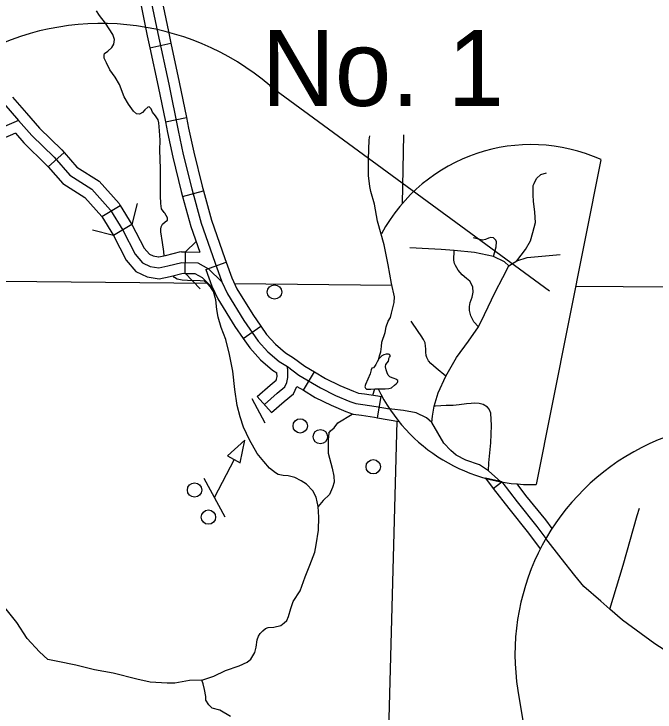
# Model space of a CAD drawing. Extents: x 22866 to 28196, y 1324810 to 1328105.
# Drawn here: x 25027.1 to 25134.1, y 1326082.2 to 1326198.9 of the extents above; entities that cross this region are included whole.
import ezdxf

# ---------------------------------------------------------------- set-up
doc = ezdxf.new("R2010")
doc.units = 0
for name, color, linetype in [('Level 31', 7, 'Continuous'), ('Level 32', 7, 'Continuous'), ('Level 35', 7, 'Continuous'), ('Level 38', 7, 'Continuous'), ('Level 45', 7, 'Continuous'), ('Level 5', 7, 'Continuous'), ('Level 56', 7, 'Continuous'), ('Level 63', 7, 'Continuous')]:
    doc.layers.add(name, color=color, linetype=linetype)

msp = doc.modelspace()

# ---------------------------------------------------------------- linework, layer by layer
at = {"layer": 'Level 31'}
for p, q in [((25108.51, 1326120.69), (25105.77, 1326121.31)), ((25107.09, 1326119.59), (25108.51, 1326120.69))]:
    msp.add_line(p, q, dxfattribs=at)
for points in [[(25102.49, 1326124.35), (25100.89, 1326125.16), (25100.02, 1326125.95), (25098.85, 1326127.19), (25096.85, 1326130.61)], [(25108.35, 1326120.72), (25106.32, 1326122.55), (25104.77, 1326123.55), (25102.49, 1326124.35)], [(25105.77, 1326121.31), (25107.09, 1326119.59)], [(25108.51, 1326120.69), (25111.08, 1326117.34), (25114.39, 1326113.23), (25115.89, 1326111.25)], [(25111.03, 1326120.36), (25112.5, 1326118.45), (25115.81, 1326114.34), (25116.9, 1326112.9)], [(25107.09, 1326119.59), (25109.67, 1326116.23), (25112.97, 1326112.12), (25114.95, 1326109.52)], [(25140.41, 1326089.55), (25137.17, 1326091.66), (25134.1, 1326093.62), (25128.65, 1326097.59), (25126.55, 1326099.42), (25125.04, 1326100.75), (25122.21, 1326103.2), (25120.69, 1326105.03), (25118.45, 1326107.93), (25115.89, 1326111.25)]]:
    msp.add_lwpolyline(points, dxfattribs=at)
at = {"layer": 'Level 32'}
for p, q in [((25049.75, 1326193.26), (25053.27, 1326194.01)), ((25052.33, 1326180.87), (25055.86, 1326181.59)), ((25032.74, 1326173.36), (25035.45, 1326175.73)), ((25055.21, 1326168.4), (25058.68, 1326169.35)), ((25041.73, 1326165.04), (25044.81, 1326166.91)), ((25059.1, 1326156.21), (25062.49, 1326157.42)), ((25065.31, 1326144.68), (25068.26, 1326146.74)), ((25075.39, 1326136.01), (25077.24, 1326139.1)), ((25070.08, 1326132.28), (25067.69, 1326134.98)), ((25087.76, 1326131.43), (25088.37, 1326134.98))]:
    msp.add_line(p, q, dxfattribs=at)
for points in [[(24974.12, 1326207.32), (24980.82, 1326207.4), (24985.53, 1326207.25), (24992.15, 1326206.59), (24999.21, 1326204.89), (25006.05, 1326202.68), (25009.21, 1326201.14), (25011.5, 1326199.59), (25013.26, 1326197.38), (25015.61, 1326193.85), (25019.15, 1326190.39), (25024.22, 1326185.16), (25027.79, 1326181.11)], [(25050.45, 1326206.43), (25051.74, 1326201.32), (25052.85, 1326195.99), (25053.27, 1326194.01)], [(25046.96, 1326205.55), (25048.23, 1326200.52), (25049.32, 1326195.25), (25049.75, 1326193.26)], [(25053.27, 1326194.01), (25054.65, 1326187.51), (25055.86, 1326181.59)], [(25049.75, 1326193.26), (25051.13, 1326186.77), (25052.33, 1326180.87)], [(25026.79, 1326184.97), (25029.15, 1326182.3), (25031.31, 1326179.82), (25035.05, 1326176.19), (25035.45, 1326175.73)], [(25027.79, 1326181.11), (25023.17, 1326179.17), (25016.86, 1326177), (25012.59, 1326175.79), (25009.07, 1326174.34), (25005.41, 1326172.55), (25002.24, 1326171.2), (24998.62, 1326169.51), (24996.24, 1326168.16), (24993.66, 1326166.82), (24991.7, 1326165.56), (24989.21, 1326163.53), (24986.97, 1326161.49), (24982.21, 1326157.07), (24980.6, 1326155.52), (24977.36, 1326152.17), (24975.08, 1326150.33), (24971.91, 1326147.77), (24969.32, 1326145.43), (24968.29, 1326144.08), (24967.32, 1326142.73)], [(25027.79, 1326181.11), (25030.01, 1326178.58), (25033.74, 1326174.95), (25036.39, 1326171.93), (25040.08, 1326169.59), (25043.17, 1326166.13), (25045.23, 1326162.75), (25047.29, 1326158.77), (25048.54, 1326157.3), (25049.8, 1326156.71), (25051.27, 1326156.49), (25052.74, 1326156.78), (25055.09, 1326157.37), (25057.74, 1326157.3), (25059.56, 1326156.31), (25061.75, 1326154.11)], [(25052.33, 1326180.87), (25052.7, 1326179.08), (25053.57, 1326174.99), (25054.99, 1326169.21), (25055.21, 1326168.4)], [(25055.86, 1326181.59), (25056.22, 1326179.81), (25057.08, 1326175.79), (25058.48, 1326170.11), (25058.68, 1326169.35)], [(25027.29, 1326178.95), (25023.81, 1326177.49), (25017.4, 1326175.28), (25016.4, 1326175)], [(25027.29, 1326178.95), (25028.7, 1326177.34), (25032.44, 1326173.71), (25032.74, 1326173.36)], [(25035.45, 1326175.73), (25037.57, 1326173.31), (25041.26, 1326170.98), (25044.63, 1326167.21), (25044.81, 1326166.91)], [(25032.74, 1326173.36), (25035.21, 1326170.55), (25038.91, 1326168.21), (25041.72, 1326165.06), (25041.73, 1326165.04)], [(25113.74, 1326168.63), (25113.77, 1326170.24), (25113.94, 1326170.59), (25114.32, 1326171.38), (25115.05, 1326172.07), (25115.98, 1326172.35)], [(25058.68, 1326169.35), (25060.02, 1326164.46), (25062.28, 1326158.01), (25062.49, 1326157.42)], [(25055.21, 1326168.4), (25056.58, 1326163.39), (25058.08, 1326159.09)], [(25111.01, 1326157.65), (25112.46, 1326159.55), (25113.29, 1326160.97), (25113.7, 1326162.38), (25114.15, 1326164.07), (25114.01, 1326165.8), (25113.84, 1326167.59), (25113.74, 1326168.63)], [(25044.81, 1326166.91), (25046.75, 1326163.72), (25043.66, 1326161.87)], [(25041.73, 1326165.04), (25043.66, 1326161.87)], [(25046.75, 1326163.72), (25048.8, 1326159.78), (25049.66, 1326158.76), (25050.32, 1326158.45), (25051.16, 1326158.32)], [(25043.66, 1326161.87), (25045.79, 1326157.76), (25047.42, 1326155.84), (25049.27, 1326154.97), (25050.62, 1326154.76)], [(25109.7, 1326156.8), (25108.98, 1326157.49), (25107.15, 1326158.35), (25103.95, 1326159.01), (25100.57, 1326159.36), (25098.39, 1326159.52), (25096.29, 1326159.63), (25093.15, 1326159.83)], [(25051.16, 1326158.32), (25051.22, 1326158.32), (25052.34, 1326158.54), (25054.89, 1326159.18), (25055.03, 1326159.17), (25055.71, 1326159.16)], [(25055.66, 1326155.55), (25055.71, 1326159.16), (25058.08, 1326159.09)], [(25109.7, 1326156.8), (25111.01, 1326157.65), (25112.74, 1326158.21), (25118.29, 1326158.72)], [(25062.49, 1326157.42), (25063.42, 1326154.8), (25064.28, 1326152.99), (25066.93, 1326148.65), (25068.26, 1326146.74)], [(25059.1, 1326156.21), (25060.09, 1326153.42), (25061.11, 1326151.28), (25063.91, 1326146.68), (25065.31, 1326144.68)], [(25096.85, 1326130.61), (25096.92, 1326131.67), (25097.2, 1326133.34), (25097.89, 1326135.57), (25099.15, 1326138.39), (25100.96, 1326141.48), (25102.96, 1326144.24), (25104.61, 1326146.6), (25105.65, 1326148.67), (25107.4, 1326152.43), (25108.7, 1326154.87), (25109.7, 1326156.8)], [(25050.62, 1326154.76), (25051.31, 1326154.66), (25053.13, 1326155.03), (25055.29, 1326155.56), (25055.29, 1326155.56), (25055.66, 1326155.55)], [(25055.66, 1326155.55), (25057.26, 1326155.51), (25058.47, 1326154.86), (25060.26, 1326153.06)], [(25068.26, 1326146.74), (25069.24, 1326145.33), (25070.71, 1326143.71), (25072.38, 1326142.28), (25073.72, 1326141.45), (25075.62, 1326140.06), (25077.24, 1326139.1)], [(25065.31, 1326144.68), (25066.42, 1326143.09), (25068.2, 1326141.12), (25070.25, 1326139.37), (25070.96, 1326138.93)], [(25068.89, 1326133.63), (25071.01, 1326135.52), (25072.27, 1326136.56), (25072.62, 1326137.3), (25072.79, 1326138.17), (25072.76, 1326139.18), (25072.71, 1326139.96)], [(25067.69, 1326134.98), (25069.84, 1326136.88), (25070.81, 1326137.69), (25070.89, 1326137.87), (25070.98, 1326138.31), (25070.96, 1326138.93)], [(25077.24, 1326139.1), (25079.09, 1326137.98), (25081.49, 1326136.8), (25083.78, 1326135.84), (25084.61, 1326135.53), (25085.59, 1326135.39), (25087.82, 1326135.08), (25088.37, 1326134.98)], [(25070.08, 1326132.28), (25072.19, 1326134.15), (25073.72, 1326135.43), (25074.31, 1326136.65)], [(25074.31, 1326136.65), (25075.39, 1326136.01)], [(25075.39, 1326136.01), (25077.36, 1326134.82), (25080, 1326133.52), (25082.47, 1326132.48), (25083.71, 1326132.03), (25085.08, 1326131.83), (25087.26, 1326131.52), (25087.76, 1326131.43)], [(25088.37, 1326134.98), (25088.54, 1326134.95)], [(25096.85, 1326130.61), (25095.95, 1326131.43), (25094.2, 1326132.23), (25092.09, 1326132.61), (25090.13, 1326132.85), (25089.78, 1326132.91)], [(25101.4, 1326133.58), (25100.37, 1326133.44), (25099.2, 1326133.48), (25097.47, 1326133.37), (25097.2, 1326133.34)], [(25106.32, 1326122.55), (25106.33, 1326123.88), (25106.67, 1326127.23), (25106.78, 1326130.13), (25106.71, 1326132.17), (25106.43, 1326132.86), (25106.12, 1326133.2), (25105.4, 1326133.62), (25104.74, 1326133.79), (25104.02, 1326133.86), (25103.43, 1326133.82), (25102.6, 1326133.76), (25101.4, 1326133.58)], [(25087.76, 1326131.43), (25091.32, 1326130.81)], [(25126.55, 1326099.42), (25128.78, 1326106.81), (25131.13, 1326115.1), (25131.51, 1326116.3)]]:
    msp.add_lwpolyline(points, dxfattribs=at)
at = {"layer": 'Level 35'}
for points in [[(25044.67, 1326187.13), (25043.94, 1326188.35), (25043.05, 1326189.55), (25042.51, 1326190.73), (25042.14, 1326191.51), (25042.14, 1326191.77), (25042.11, 1326192.04), (25042.19, 1326192.3), (25042.74, 1326192.66), (25043.42, 1326193.27), (25043.73, 1326193.87), (25043.84, 1326194.65), (25043.58, 1326195.44), (25042.35, 1326197.37), (25041.36, 1326198.63), (25040.86, 1326199.41)], [(25052.12, 1326165.73), (25051.7, 1326166.34), (25051.6, 1326167.21), (25051.54, 1326168.51), (25051.54, 1326170.95), (25051.54, 1326173.07), (25051.39, 1326176.13), (25051.44, 1326177.78), (25051.36, 1326179.37), (25051.26, 1326180.68), (25051.13, 1326181.22), (25050.66, 1326181.87), (25050.16, 1326182.5), (25049.95, 1326183.07), (25049.61, 1326183.36), (25049.4, 1326183.31), (25048.88, 1326182.87), (25048.49, 1326182.45), (25048.04, 1326182.16), (25047.52, 1326182.19), (25047, 1326182.63), (25046.16, 1326183.81), (25045.48, 1326185.04), (25044.67, 1326187.13)], [(25090.59, 1326151.65), (25090.12, 1326153.86), (25089.55, 1326156.95), (25088.85, 1326160.33), (25087.78, 1326164.26), (25087.28, 1326167.11), (25086.64, 1326169.22), (25086.47, 1326170.04), (25086.27, 1326171.89), (25086.24, 1326174.64), (25086.37, 1326177.85), (25086.47, 1326178.54)], [(25052.15, 1326158.5), (25052.07, 1326159.19), (25051.86, 1326160.71), (25051.57, 1326162.46), (25051.57, 1326162.91), (25051.65, 1326163.35), (25051.88, 1326163.77), (25052.28, 1326164.14), (25052.67, 1326164.45), (25052.69, 1326164.82), (25052.49, 1326165.21), (25052.22, 1326165.6), (25052.12, 1326165.73)], [(25059.23, 1326153.96), (25058.86, 1326154.25), (25058.13, 1326154.3), (25056.04, 1326154.35), (25055.13, 1326154.41), (25054.31, 1326154.59), (25053.87, 1326154.85), (25053.65, 1326155.15)], [(25063.93, 1326136.13), (25063.59, 1326139.2), (25063.07, 1326141.97), (25062.42, 1326144.48), (25061.63, 1326146.5), (25061.14, 1326148.22), (25060.95, 1326149.5), (25060.74, 1326151.13), (25060.37, 1326152.5), (25059.95, 1326153.19), (25059.23, 1326153.96)], [(25087.99, 1326141.26), (25088.11, 1326141.76), (25088.31, 1326142.43), (25088.41, 1326143.3), (25088.48, 1326144.07), (25089.02, 1326145.68), (25089.18, 1326146.62), (25089.52, 1326147.56), (25089.92, 1326148.16), (25090.12, 1326148.9), (25090.26, 1326149.57), (25090.56, 1326150.68), (25090.59, 1326151.65)], [(25087.66, 1326136.25), (25089.06, 1326136.23), (25089.67, 1326136.28), (25090.12, 1326136.42), (25090.61, 1326136.88), (25090.87, 1326137.1), (25091.1, 1326137.3), (25091.15, 1326137.5), (25091.13, 1326137.66), (25090.8, 1326137.89), (25090.52, 1326137.99), (25090.19, 1326138.08), (25089.81, 1326138.24), (25089.55, 1326138.55), (25089.39, 1326138.94), (25089.2, 1326139.41), (25089.09, 1326139.93), (25089.09, 1326140), (25089.16, 1326140.33), (25089.37, 1326140.58), (25089.62, 1326140.89), (25089.63, 1326141.17), (25089.63, 1326141.31), (25089.74, 1326141.52), (25089.93, 1326141.78), (25089.77, 1326141.97), (25089.58, 1326142.02), (25089.18, 1326142.02), (25088.83, 1326141.94), (25088.48, 1326141.74), (25087.99, 1326141.26), (25087.72, 1326140.75), (25087.49, 1326140.3), (25087.28, 1326139.96), (25087.09, 1326139.76), (25086.84, 1326139.7), (25086.72, 1326139.41), (25086.53, 1326138.78), (25086.15, 1326137.84), (25085.73, 1326136.98), (25085.64, 1326136.58), (25085.73, 1326136.37), (25085.92, 1326136.18), (25086.62, 1326136.18), (25087.3, 1326136.27), (25087.7, 1326136.27)], [(25086.96, 1326135.2), (25087.3, 1326136.27)], [(25077.52, 1326110.16), (25077.91, 1326112.63), (25077.94, 1326114.82), (25077.83, 1326116.6), (25077.49, 1326118.12), (25076.97, 1326119.19), (25075.9, 1326120.34), (25075.03, 1326120.89), (25073.94, 1326121.42), (25072.84, 1326121.73), (25072, 1326121.78), (25071.17, 1326121.94), (25070.72, 1326122.2), (25069.7, 1326122.99), (25068.76, 1326124.09), (25067.66, 1326125.47), (25066.36, 1326127.73), (25065.39, 1326129.85), (25064.81, 1326131.58), (25064.34, 1326133.44), (25063.93, 1326136.13)], [(25079.64, 1326128.85), (25079.91, 1326129.25), (25080.51, 1326129.76), (25081.11, 1326130.56), (25083.52, 1326132.04), (25083.61, 1326132.06)], [(25079.64, 1326128.85), (25079.51, 1326127.8), (25079.54, 1326125.52), (25080.17, 1326123), (25080.48, 1326121.63), (25080.51, 1326120.66), (25080.24, 1326119.75), (25079.77, 1326118.58), (25078.7, 1326117.61), (25077.83, 1326116.6)], [(25058.42, 1326087.58), (25060.4, 1326088.25), (25062.36, 1326089.19), (25064.66, 1326089.95), (25065.97, 1326090.58), (25066.62, 1326091.07), (25067.25, 1326092.17), (25067.49, 1326093.09), (25067.67, 1326094.32), (25067.88, 1326094.92), (25068.19, 1326095.36), (25068.61, 1326095.81), (25069.05, 1326096.2), (25069.5, 1326096.38), (25070.44, 1326096.44), (25071.59, 1326096.72), (25072.19, 1326097.12), (25072.64, 1326097.56), (25072.92, 1326098.19), (25073.29, 1326099.55), (25073.68, 1326100.69), (25074.85, 1326102.47), (25075.66, 1326104.85), (25076.47, 1326106.78), (25077.28, 1326108.96), (25077.52, 1326110.16)], [(25058.42, 1326087.58), (25056.35, 1326087.52), (25053.93, 1326087.09), (25052.64, 1326087.09), (25049.79, 1326087.23), (25047.58, 1326087.73), (25043.59, 1326088.73), (25040.52, 1326089.3), (25037.38, 1326090.09), (25034.39, 1326090.66), (25032.68, 1326091.02), (25031.32, 1326092.3), (25029.26, 1326094.51), (25027.54, 1326097.23), (25022.12, 1326103.86), (25019.99, 1326106.5)], [(25063.19, 1326081.5), (25061.42, 1326082.53), (25060.17, 1326082.9), (25059.57, 1326083.42), (25059.1, 1326084.23), (25059.07, 1326084.86), (25058.89, 1326086.01), (25058.62, 1326086.95), (25058.42, 1326087.58)]]:
    msp.add_lwpolyline(points, dxfattribs=at)
at = {"layer": 'Level 38'}
for points in [[(25047.64, 1326167.2), (25046.75, 1326163.71)], [(25043.66, 1326161.87), (25040.17, 1326162.76)], [(25055.71, 1326159.16), (25057.47, 1326160.86)], [(25058.15, 1326152.97), (25055.65, 1326155.56)]]:
    msp.add_lwpolyline(points, dxfattribs=at)
at = {"layer": 'Level 45'}
for points in [[(25043.79, 1326225.73), (25044.18, 1326221.96), (25045.12, 1326218.19), (25046.69, 1326213.56), (25048.18, 1326208.06), (25049.99, 1326200.92), (25051.09, 1326195.62), (25052.89, 1326187.14), (25054.46, 1326179.44), (25055.32, 1326175.39), (25056.73, 1326169.66), (25058.3, 1326163.93), (25060.58, 1326157.41), (25061.75, 1326154.11)], [(25107.15, 1326158.35), (25107.57, 1326159.97), (25107.64, 1326160.8), (25107.53, 1326161.08), (25107.12, 1326161.49), (25106.7, 1326161.53), (25106.29, 1326161.42), (25105.77, 1326161.18), (25105.32, 1326161.08), (25103.81, 1326161.49)], [(25104.61, 1326146.6), (25103.84, 1326147.45), (25103.32, 1326148.45), (25103.12, 1326149.35), (25103.12, 1326150.01), (25103.26, 1326150.66), (25103.57, 1326151.59), (25103.74, 1326152.39), (25103.67, 1326153.25), (25103.43, 1326153.87), (25103.19, 1326154.25), (25102.63, 1326154.7), (25101.88, 1326155.32), (25101.24, 1326156.1), (25100.81, 1326156.84), (25100.6, 1326157.22), (25100.5, 1326157.74), (25100.57, 1326159.36)], [(25061.75, 1326154.11), (25062.69, 1326152.14), (25065.42, 1326147.66), (25067.83, 1326144.21), (25069.45, 1326142.42), (25071.32, 1326140.83), (25072.71, 1326139.96)], [(25099.15, 1326138.39), (25097.56, 1326139.73), (25096.67, 1326140.49), (25096.25, 1326140.94), (25095.98, 1326141.46), (25095.88, 1326141.81), (25095.81, 1326142.36), (25095.81, 1326142.91), (25095.77, 1326143.39), (25095.7, 1326143.95), (25095.46, 1326144.5), (25095.05, 1326145.12), (25094.53, 1326145.84), (25093.36, 1326147.54)], [(25072.71, 1326139.96), (25074.63, 1326138.56), (25078.23, 1326136.4), (25080.74, 1326135.16), (25083.12, 1326134.16), (25084.16, 1326133.78), (25085.33, 1326133.61), (25087.54, 1326133.3), (25089.78, 1326132.91)]]:
    msp.add_lwpolyline(points, dxfattribs=at)
at = {"layer": 'Level 5'}
for points in [[(25091.92, 1326167.23), (25092.17, 1326178.7)], [(25059.47, 1326153.85), (25019.39, 1326154.27), (24981.29, 1326153.64)], [(25090.18, 1326153.54), (25063.89, 1326153.81)], [(25144.72, 1326153.19), (25120.85, 1326153.34)], [(25088.36, 1326031.4), (25091.03, 1326130.86)]]:
    msp.add_lwpolyline(points, dxfattribs=at)
at = {"layer": 'Level 56'}
msp.add_line((25063.85, 1326124.43), (25060.5, 1326118.05), dxfattribs=at)
for points in [[(25066.78, 1326134.64), (25068.96, 1326130.58)], [(25058.78, 1326121.33), (25062.26, 1326114.84)]]:
    msp.add_lwpolyline(points, dxfattribs=at)
msp.add_lwpolyline([(25062.7, 1326125.07), (25064.82, 1326123.86), (25065.58, 1326127.66)], close=True, dxfattribs=at)
for centre in [(25070.56, 1326152.43), (25074.85, 1326130.06), (25078.22, 1326128.25), (25087.05, 1326123.23), (25057.21, 1326119.34), (25059.53, 1326114.81)]:
    msp.add_circle(centre, 1.2, dxfattribs=at)
at = {"layer": 'Level 63'}
for p, q in [((25069.8, 1326186.91), (25116.47, 1326152.61)), ((25125.08, 1326174.54), (25114.24, 1326120.27)), ((25111.19, 1326085.82), (25116.58, 1326053.07))]:
    msp.add_line(p, q, dxfattribs=at)
for centre, radius, start, end in [((25041.66, 1326153.97), 43.33, 49.5013, 189.0036), ((25113.41, 1326148.66), 28.4, 65.7193, 151.6006), ((25113.41, 1326148.66), 28.4, 205.8758, 271.6746), ((25149.5, 1326091.89), 38.78, 49.5013, 189.0036)]:
    msp.add_arc(centre, radius, start, end, dxfattribs=at)

# ---------------------------------------------------------------- texts
msp.add_text('No. 1', height=12.674, dxfattribs=at).set_placement((25068.39, 1326183.53))

doc.saveas('drawing.dxf')
